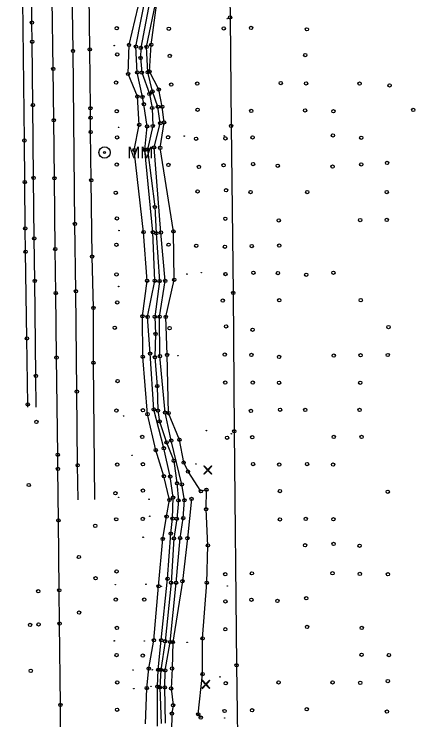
# Model space of a CAD drawing. Extents: x 20503438 to 20508873, y 7964251 to 7984667.
# Drawn here: x 20505454.4 to 20505695.9, y 7981861 to 7982286.2 of the extents above; entities that cross this region are included whole.
import ezdxf

# ---------------------------------------------------------------- set-up
doc = ezdxf.new("R2010")
doc.units = 0
for name, color, linetype in [('SurBreakLine', 7, 'Continuous'), ('SurControl', 7, 'Continuous'), ('SurDrainageArrowUp', 7, 'Continuous'), ('SurEdgeRoadPaved', 7, 'Continuous'), ('SurEdgeShoulderPaved', 7, 'Continuous'), ('SurFenceWire', 7, 'Continuous'), ('SurPointsNonDTM', 7, 'Continuous'), ('SurRoadPoints', 7, 'Continuous'), ('SurSurveyPoints', 7, 'Continuous')]:
    doc.layers.add(name, color=color, linetype=linetype)

msp = doc.modelspace()

# ---------------------------------------------------------------- linework, layer by layer
at = {"layer": 'SurBreakLine'}
for points in [[(20505533.66, 7981858.56), (20505534.37, 7981880.13), (20505535.54, 7981891.92), (20505538.65, 7981908.97), (20505541.43, 7981941.46), (20505544, 7981970.04), (20505546.31, 7981983.42), (20505548.03, 7981993.51), (20505544.72, 7982007.73), (20505539.77, 7982023.51), (20505534.8, 7982045.17), (20505531.92, 7982079.77), (20505531.73, 7982104.19), (20505534.58, 7982125.53), (20505532.44, 7982154.9), (20505526.86, 7982204.31), (20505529.86, 7982219.58), (20505528.68, 7982236.47), (20505523.06, 7982250.12), (20505523.65, 7982267.68), (20505531.03, 7982298.4)], [(20505540.86, 7981857.16), (20505540.73, 7981881.04), (20505541.27, 7981891.19), (20505543.11, 7981908.93), (20505546.87, 7981946.01), (20505548.79, 7981973.2), (20505549.87, 7981982.29), (20505550.18, 7981994.89), (20505548.49, 7982007.54), (20505544.64, 7982024.62), (20505538.6, 7982048.07), (20505536.39, 7982081.69), (20505534.88, 7982103.73), (20505539.2, 7982125.55), (20505538.07, 7982154.79), (20505533.09, 7982204.37), (20505534.53, 7982218.56), (20505532.62, 7982231.85), (20505531.72, 7982236.28), (20505528.58, 7982251.08), (20505527.86, 7982266.64), (20505534.23, 7982299.42)], [(20505482.66, 7981838.18), (20505482.35, 7981869.99), (20505481.84, 7981919), (20505481.63, 7981939.03), (20505481.16, 7981981.15), (20505480.82, 7982012.22), (20505480.73, 7982020.7), (20505479.97, 7982079.23), (20505479.51, 7982118.14), (20505479.21, 7982144.63), (20505478.7, 7982187.28), (20505478.32, 7982222.25), (20505478.02, 7982253.21), (20505477.45, 7982295.16)], [(20505545.64, 7981858.92), (20505545.16, 7981880.55), (20505545.45, 7981890.75), (20505548.44, 7981907.9), (20505552.02, 7981943.58), (20505554.39, 7981970.53), (20505556.38, 7981982.54), (20505557.08, 7981993.33), (20505555.48, 7982002.81), (20505549.12, 7982029.29), (20505545.37, 7982046.14), (20505542.28, 7982080.11), (20505542.08, 7982103.84), (20505545.47, 7982125.46), (20505542.85, 7982154.62), (20505538.74, 7982205.85), (20505542.5, 7982220.43), (20505541.11, 7982230.43), (20505537.79, 7982239.62), (20505534.95, 7982251.19), (20505534.2, 7982266.46), (20505540.46, 7982296.4)], [(20505566.86, 7981862.36), (20505565.41, 7981864.32), (20505567.96, 7981888.53), (20505568.01, 7981910.06), (20505570.48, 7981943.64), (20505571.16, 7981966.05), (20505570.1, 7981987.9), (20505570.34, 7981999.63), (20505566.96, 7981998.68), (20505559.2, 7982010.61), (20505556.59, 7982016.02), (20505554.01, 7982029.73), (20505547.49, 7982045.85), (20505546.56, 7982080.9), (20505545.76, 7982103.77), (20505550.95, 7982126.11), (20505550.41, 7982155.27), (20505542.43, 7982205.63), (20505544.81, 7982220.91), (20505543.66, 7982230.41), (20505541.61, 7982240.76), (20505535.97, 7982251.65), (20505537.1, 7982267.72), (20505540.88, 7982296.21)], [(20505561.36, 7981994.08), (20505558.88, 7981970.37), (20505555.83, 7981944.51), (20505549.98, 7981907.82), (20505549.62, 7981891.93), (20505549, 7981879.91), (20505550.23, 7981869.81), (20505549.51, 7981864.77), (20505549.3, 7981853.83), (20505549.91, 7981848.75), (20505553.2, 7981847.61)]]:
    msp.add_lwpolyline(points, dxfattribs=at)
at = {"layer": 'SurControl'}
for points in [[(20505573.56, 7982013.74), (20505573.3, 7982013.99), (20505571.16, 7982011.77), (20505569.02, 7982013.99), (20505568.76, 7982013.74), (20505570.91, 7982011.51), (20505568.76, 7982009.28), (20505569.02, 7982009.03), (20505571.16, 7982011.25), (20505573.3, 7982009.03), (20505573.56, 7982009.28), (20505571.41, 7982011.51)], [(20505572.41, 7981884.62), (20505572.15, 7981884.87), (20505570.01, 7981882.65), (20505567.87, 7981884.87), (20505567.61, 7981884.62), (20505569.76, 7981882.39), (20505567.61, 7981880.16), (20505567.87, 7981879.91), (20505570.01, 7981882.13), (20505572.15, 7981879.91), (20505572.41, 7981880.16), (20505570.26, 7981882.39)]]:
    msp.add_lwpolyline(points, close=True, dxfattribs=at)
for centre in [(20505582.84, 7982283.42), (20505514.72, 7982267.28), (20505517.35, 7982218.01), (20505556.9, 7982212.68), (20505581.02, 7982212.82), (20505517.64, 7982155.82), (20505558.52, 7982129.53), (20505567.24, 7982130.47), (20505581.09, 7982129.57), (20505517.46, 7982122.09), (20505553.1, 7982080.44), (20505520.36, 7982044.02), (20505570.32, 7982035.3), (20505585.33, 7982033.33), (20505525.55, 7982020.33), (20505563.96, 7982015.1), (20505517.45, 7981995.11), (20505535.78, 7981993.92), (20505536.18, 7981983.69), (20505532.19, 7981971.05), (20505515.45, 7981942.49), (20505533.81, 7981942.73), (20505543.03, 7981941.44), (20505582.85, 7981941.69), (20505514.74, 7981908.6), (20505532.92, 7981908.53), (20505558.7, 7981907.75), (20505526.13, 7981891.07), (20505537.66, 7981891.18), (20505578.49, 7981886.9), (20505536.86, 7981881.23), (20505526.56, 7981879.81), (20505581.34, 7981862.1)]:
    msp.add_circle(centre, 0.15, dxfattribs=at)
at = {"layer": 'SurDrainageArrowUp'}
msp.add_lwpolyline([(20505536.79, 7982297.77), (20505530.73, 7982265.81), (20505530.59, 7982259.82), (20505531.33, 7982250.97), (20505535.93, 7982238.11), (20505537.61, 7982229.63), (20505537.92, 7982218.79), (20505534.78, 7982204.62), (20505539.23, 7982169.99), (20505540.07, 7982154.17), (20505542.1, 7982125.32), (20505539.21, 7982103.89), (20505539.68, 7982093.54), (20505539.25, 7982079.46), (20505540.64, 7982062.1), (20505541.1, 7982047.32), (20505542.09, 7982040.78), (20505546.28, 7982028.14), (20505550.66, 7982017.09), (20505552.57, 7982003.52), (20505553.43, 7981993.22), (20505552.45, 7981982.2), (20505550.72, 7981970.32), (20505548.99, 7981943.58), (20505545.4, 7981908.32), (20505542.77, 7981891.09), (20505542.19, 7981880.5), (20505542.98, 7981858.88)], dxfattribs=at)
at = {"layer": 'SurEdgeRoadPaved'}
for points in [[(20505492.99, 7981993.59), (20505492.72, 7982014.35), (20505492.22, 7982058.8), (20505491.71, 7982119.25), (20505491.09, 7982159.8), (20505489.91, 7982264.01), (20505489.66, 7982289.18), (20505487.48, 7982484.19), (20505486.86, 7982538.99), (20505486.36, 7982623.82), (20505485.4, 7982711.25), (20505484.93, 7982775.73), (20505484.31, 7982835.82)], [(20505467.81, 7982049.46), (20505467.61, 7982068.18), (20505466.87, 7982125.48), (20505466.54, 7982151.08), (20505466.17, 7982187.53), (20505465.76, 7982231.38), (20505465.31, 7982269.59), (20505465.16, 7982281.14), (20505464.61, 7982327.96), (20505463.62, 7982409.11), (20505462.56, 7982525.93), (20505461.58, 7982636.16), (20505461.28, 7982673.07), (20505460.57, 7982745.92), (20505460.02, 7982819.87)]]:
    msp.add_lwpolyline(points, dxfattribs=at)
at = {"layer": 'SurEdgeShoulderPaved'}
for points in [[(20505503.12, 7981993.7), (20505502.21, 7982076.11), (20505502.21, 7982109.18), (20505501.39, 7982140.13), (20505500.91, 7982186.13), (20505500.55, 7982215.12), (20505500.48, 7982223.74), (20505500.44, 7982229.48), (20505500.04, 7982264.96), (20505498.78, 7982363.61), (20505498.7, 7982393.65), (20505498.03, 7982438.84), (20505497.19, 7982508.63), (20505496.45, 7982610.94), (20505496.22, 7982654.28), (20505495.42, 7982717.71), (20505495.4, 7982754.06), (20505495.09, 7982782.36), (20505493.62, 7982896.29)], [(20505462.63, 7982049.4), (20505462.61, 7982051), (20505462.11, 7982090.85), (20505461.3, 7982143.05), (20505461.11, 7982157.07), (20505460.83, 7982185.02), (20505460.68, 7982210.05), (20505459.25, 7982328.4), (20505458.74, 7982376.86), (20505458.32, 7982412.29), (20505458.06, 7982438.23), (20505457.12, 7982523.38), (20505456.64, 7982592.43), (20505456.16, 7982626.15), (20505455.68, 7982697.33), (20505455.16, 7982733.14), (20505454.87, 7982799.91), (20505454.43, 7982834.05)]]:
    msp.add_lwpolyline(points, dxfattribs=at)
at = {"layer": 'SurFenceWire'}
msp.add_lwpolyline([(20505583.74, 7982820.12), (20505580.19, 7982701.02), (20505581.22, 7982574.25), (20505581.59, 7982491.04), (20505582.46, 7982428.28), (20505582.73, 7982421.79), (20505583.15, 7982367.8), (20505584.54, 7982284.18), (20505585.13, 7982218.82), (20505586.48, 7982118.26), (20505587.09, 7982034.84), (20505588.49, 7981893.92), (20505589.47, 7981822.49), (20505590.29, 7981766.07)], dxfattribs=at)
at = {"layer": 'SurPointsNonDTM'}
for centre in [(20505584.54, 7982284.18), (20505585.13, 7982218.82), (20505586.48, 7982118.26), (20505587.09, 7982034.84), (20505588.49, 7981893.92)]:
    msp.add_circle(centre, 1, dxfattribs=at)
at = {"layer": 'SurRoadPoints'}
for radius in [3.43, 0.571]:
    msp.add_circle((20505508.95, 7982202.84), radius, dxfattribs=at)
at = {"layer": 'SurSurveyPoints'}
for centre in [(20505465.16, 7982281.14), (20505516.29, 7982277.65), (20505547.65, 7982277.34), (20505580.77, 7982277.54), (20505597.21, 7982277.89), (20505630.85, 7982277.03), (20505465.31, 7982269.59), (20505523.65, 7982267.68), (20505527.86, 7982266.64), (20505537.1, 7982267.72), (20505489.91, 7982264.01), (20505500.04, 7982264.96), (20505530.73, 7982265.81), (20505534.2, 7982266.46), (20505516.6, 7982261.93), (20505530.59, 7982259.82), (20505548.16, 7982261.04), (20505629.88, 7982261.54), (20505478.02, 7982253.21), (20505523.06, 7982250.12), (20505528.58, 7982251.08), (20505531.33, 7982250.97), (20505534.95, 7982251.19), (20505535.97, 7982251.65), (20505515.88, 7982244.99), (20505549.12, 7982243.73), (20505564.75, 7982244.37), (20505615.04, 7982244.66), (20505630.34, 7982244.46), (20505662.56, 7982244.37), (20505680.64, 7982243.27), (20505535.93, 7982238.11), (20505537.79, 7982239.62), (20505541.61, 7982240.76), (20505528.68, 7982236.47), (20505531.72, 7982236.28), (20505465.76, 7982231.38), (20505500.44, 7982229.48), (20505532.62, 7982231.85), (20505537.61, 7982229.63), (20505541.11, 7982230.43), (20505543.66, 7982230.41), (20505565, 7982228.57), (20505694.9, 7982228.5), (20505516.27, 7982227.65), (20505597.29, 7982227.83), (20505629.73, 7982228.22), (20505646.83, 7982227.71), (20505478.32, 7982222.25), (20505500.48, 7982223.74), (20505542.5, 7982220.43), (20505544.81, 7982220.91), (20505529.86, 7982219.58), (20505534.53, 7982218.56), (20505537.92, 7982218.79), (20505500.55, 7982215.12), (20505516.47, 7982211.87), (20505547.16, 7982212.03), (20505581.71, 7982211.31), (20505598.09, 7982211.92), (20505646.49, 7982213.12), (20505663.57, 7982211.75), (20505460.68, 7982210.05), (20505564.08, 7982211.13), (20505526.86, 7982204.31), (20505533.09, 7982204.37), (20505534.78, 7982204.62), (20505538.74, 7982205.85), (20505542.43, 7982205.63), (20505516.3, 7982195.54), (20505547.38, 7982195.37), (20505580.63, 7982195.11), (20505598.42, 7982195.82), (20505613.26, 7982194.84), (20505646.35, 7982194.38), (20505663.59, 7982195.68), (20505679.18, 7982196.5), (20505565.81, 7982194.17), (20505466.17, 7982187.53), (20505478.7, 7982187.28), (20505500.91, 7982186.13), (20505460.83, 7982185.02), (20505515.7, 7982178.59), (20505564.96, 7982179.41), (20505582.13, 7982180.08), (20505596.95, 7982179.01), (20505631.01, 7982178.97), (20505678.91, 7982178.99), (20505539.23, 7982169.99), (20505516.39, 7982163.09), (20505581.69, 7982162.92), (20505613.86, 7982161.9), (20505662.93, 7982162.06), (20505678.98, 7982162.21), (20505461.11, 7982157.07), (20505491.09, 7982159.8), (20505532.44, 7982154.9), (20505538.07, 7982154.79), (20505540.07, 7982154.17), (20505542.85, 7982154.62), (20505550.41, 7982155.27), (20505466.54, 7982151.08), (20505479.21, 7982144.63), (20505516.11, 7982147.23), (20505547.52, 7982147.29), (20505564.14, 7982146.67), (20505581.47, 7982146.06), (20505597.57, 7982146.47), (20505614.17, 7982146.76), (20505461.3, 7982143.05), (20505501.39, 7982140.13), (20505516.12, 7982129.33), (20505581.75, 7982129.59), (20505598.62, 7982130.36), (20505613.35, 7982130.19), (20505630.47, 7982129.13), (20505646.79, 7982130.38), (20505466.87, 7982125.48), (20505534.58, 7982125.53), (20505539.2, 7982125.55), (20505542.1, 7982125.32), (20505545.47, 7982125.46), (20505550.95, 7982126.11), (20505479.51, 7982118.14), (20505491.71, 7982119.25), (20505580.18, 7982113.57), (20505614.17, 7982113.83), (20505663.31, 7982113.85), (20505516.56, 7982112.47), (20505502.21, 7982109.18), (20505531.73, 7982104.19), (20505534.88, 7982103.73), (20505539.21, 7982103.89), (20505542.08, 7982103.84), (20505545.76, 7982103.77), (20505515.1, 7982097.21), (20505548.06, 7982096.98), (20505582.11, 7982098.06), (20505680, 7982097.63), (20505539.68, 7982093.54), (20505598.09, 7982096.03), (20505462.11, 7982090.85), (20505531.92, 7982079.77), (20505536.39, 7982081.69), (20505539.25, 7982079.46), (20505542.28, 7982080.11), (20505546.56, 7982080.9), (20505581.37, 7982081.09), (20505597.45, 7982080.85), (20505614.12, 7982079.62), (20505647.04, 7982080.51), (20505663.18, 7982080.62), (20505679.54, 7982080.82), (20505479.97, 7982079.23), (20505502.21, 7982076.11), (20505467.61, 7982068.18), (20505516.75, 7982065.13), (20505581.61, 7982064.18), (20505598.21, 7982064.22), (20505614.09, 7982064.07), (20505662.95, 7982064.11), (20505492.22, 7982058.8), (20505540.64, 7982062.1), (20505462.61, 7982051), (20505516.08, 7982047.34), (20505532.05, 7982047.53), (20505538.6, 7982048.07), (20505541.1, 7982047.32), (20505545.37, 7982046.14), (20505547.49, 7982045.85), (20505597.08, 7982047.17), (20505614.67, 7982047.87), (20505629.82, 7982047.77), (20505662.62, 7982047.75), (20505534.8, 7982045.17), (20505467.91, 7982040.47), (20505542.09, 7982040.78), (20505531.65, 7982031.42), (20505549.12, 7982029.29), (20505554.01, 7982029.73), (20505582.76, 7982030.95), (20505597.92, 7982031.27), (20505647, 7982031.5), (20505663.77, 7982031.48), (20505544.64, 7982024.62), (20505546.28, 7982028.14), (20505480.73, 7982020.7), (20505539.77, 7982023.51), (20505550.66, 7982017.09), (20505556.59, 7982016.02), (20505480.82, 7982012.22), (20505492.72, 7982014.35), (20505516.54, 7982014.79), (20505532.01, 7982014.96), (20505598.38, 7982015.1), (20505614.15, 7982014.75), (20505630.92, 7982015.12), (20505646.63, 7982014.75), (20505544.72, 7982007.73), (20505548.49, 7982007.54), (20505559.2, 7982010.61), (20505552.57, 7982003.52), (20505463.22, 7982002.49), (20505531.99, 7981999.17), (20505555.48, 7982002.81), (20505566.96, 7981998.68), (20505570.34, 7981999.63), (20505614.62, 7981998.86), (20505515.42, 7981997.51), (20505550.18, 7981994.89), (20505679.55, 7981998.4), (20505548.03, 7981993.51), (20505553.43, 7981993.22), (20505557.08, 7981993.33), (20505561.36, 7981994.08), (20505570.1, 7981987.9), (20505516, 7981981.81), (20505531.98, 7981982.02), (20505546.31, 7981983.42), (20505549.87, 7981982.29), (20505552.45, 7981982.2), (20505556.38, 7981982.54), (20505614.58, 7981981.73), (20505630.17, 7981982.04), (20505646.82, 7981981.84), (20505481.16, 7981981.15), (20505503.3, 7981977.89), (20505548.79, 7981973.2), (20505544, 7981970.04), (20505550.72, 7981970.32), (20505554.39, 7981970.53), (20505558.88, 7981970.37), (20505571.16, 7981966.05), (20505629.73, 7981966.18), (20505646.87, 7981967.03), (20505662.59, 7981965.89), (20505493.44, 7981959.11), (20505516.14, 7981950.4), (20505581.6, 7981948.74), (20505597.72, 7981949.27), (20505646.26, 7981949.31), (20505662.73, 7981948.96), (20505679.69, 7981948.73), (20505503.51, 7981946.34), (20505546.87, 7981946.01), (20505548.99, 7981943.58), (20505552.02, 7981943.58), (20505555.83, 7981944.51), (20505570.48, 7981943.64), (20505541.43, 7981941.46), (20505468.96, 7981938.47), (20505481.63, 7981939.03), (20505515.64, 7981933.45), (20505532.86, 7981933.5), (20505581.76, 7981932.33), (20505597.37, 7981933.31), (20505613.05, 7981932.69), (20505630.49, 7981934.22), (20505493.61, 7981925.64), (20505464.05, 7981918.16), (20505469.2, 7981918.48), (20505481.84, 7981919), (20505516.37, 7981916.41), (20505581.69, 7981915.62), (20505630.93, 7981917.03), (20505663.92, 7981916.37), (20505568.01, 7981910.06), (20505538.65, 7981908.97), (20505543.11, 7981908.93), (20505545.4, 7981908.32), (20505548.44, 7981907.9), (20505549.98, 7981907.82), (20505516.18, 7981900.04), (20505531.92, 7981899.74), (20505663.81, 7981900.24), (20505680.29, 7981900.03), (20505464.43, 7981890.53), (20505535.54, 7981891.92), (20505541.27, 7981891.19), (20505542.77, 7981891.09), (20505545.45, 7981890.75), (20505549.62, 7981891.93), (20505567.96, 7981888.53), (20505679.6, 7981884.37), (20505516.58, 7981883.51), (20505534.37, 7981880.13), (20505540.73, 7981881.04), (20505542.19, 7981880.5), (20505545.16, 7981880.55), (20505549, 7981879.91), (20505581.95, 7981883.08), (20505613.81, 7981883.55), (20505646.34, 7981883.54), (20505662.94, 7981883.3), (20505482.35, 7981869.99), (20505516.46, 7981867.09), (20505550.23, 7981869.81), (20505630.75, 7981867.41), (20505549.51, 7981864.77), (20505565.41, 7981864.32), (20505581.24, 7981866.33), (20505597.79, 7981866.75), (20505679.05, 7981865.98), (20505566.86, 7981862.36)]:
    msp.add_circle(centre, 1, dxfattribs=at)

# ---------------------------------------------------------------- texts
at = {"layer": 'SurRoadPoints'}
msp.add_text('MM', height=6.995, rotation=360, dxfattribs=at).set_placement((20505522.66, 7982199.35))

doc.saveas('drawing.dxf')
